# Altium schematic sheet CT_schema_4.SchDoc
size 282 x 169 mm
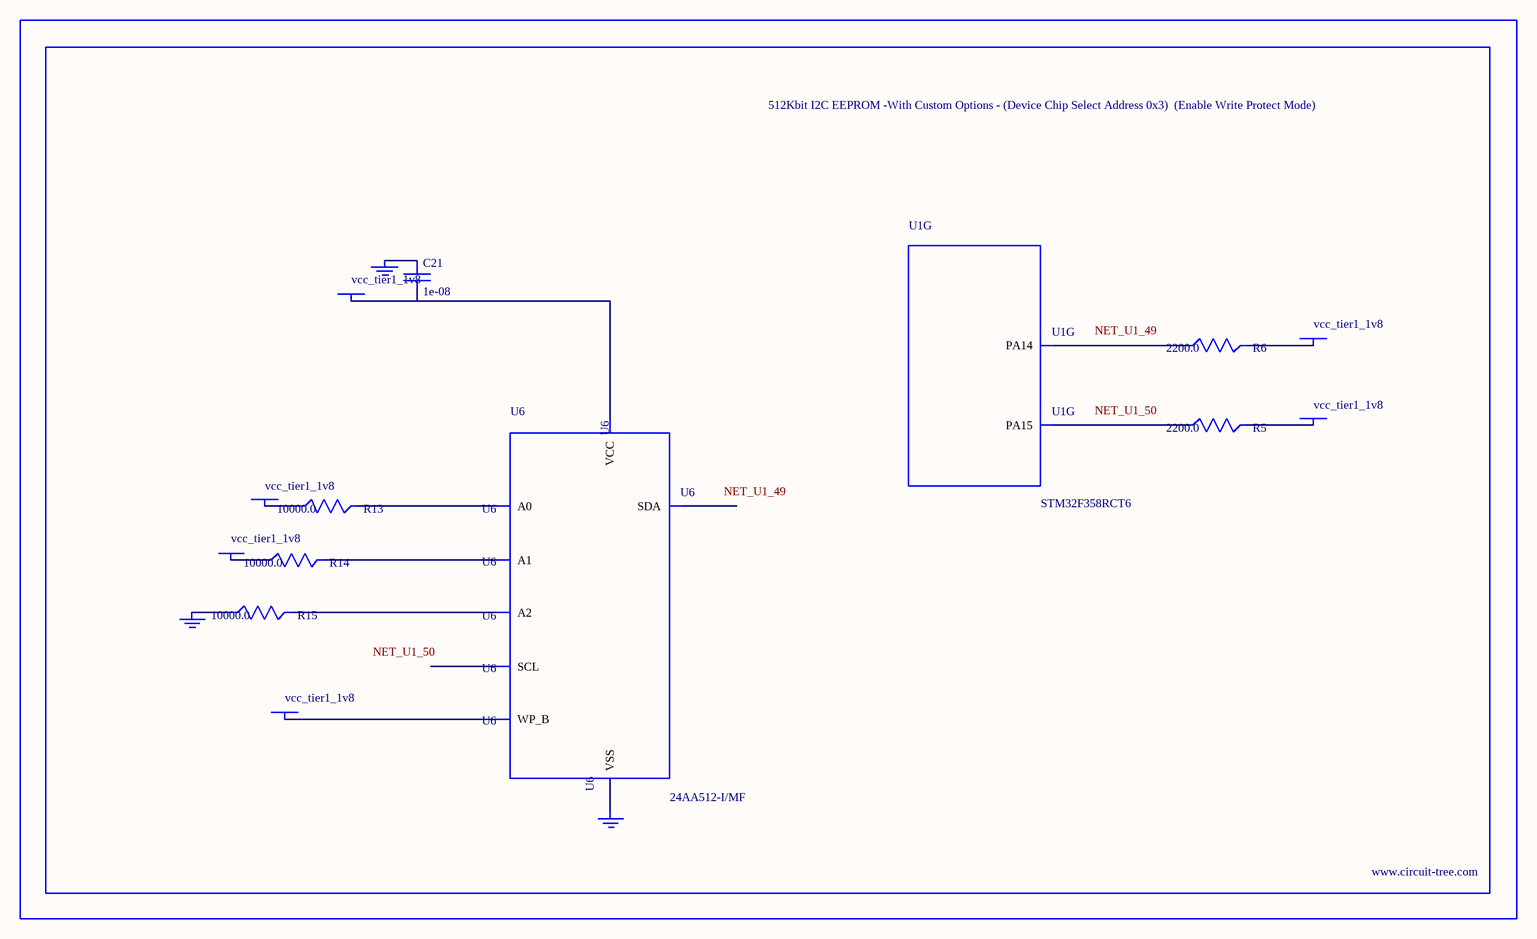
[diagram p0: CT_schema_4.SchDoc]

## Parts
BORDER3  (no value)
C21  1e-08  [C0402]
GND_INSTANCE_3_0  (no value)
GND_INSTANCE_3_1  (no value)
GND_INSTANCE_3_2  (no value)
POWER_INSTANCE_3_0  vcc_tier1_1v8
POWER_INSTANCE_3_1  vcc_tier1_1v8
POWER_INSTANCE_3_2  vcc_tier1_1v8
POWER_INSTANCE_3_3  vcc_tier1_1v8
POWER_INSTANCE_3_4  vcc_tier1_1v8
POWER_INSTANCE_3_5  vcc_tier1_1v8
R5  2200.0  [R0603]
R6  2200.0  [R0603]
R13  10000.0  [R0603]
R14  10000.0  [R0603]
R15  10000.0  [R0603]
U1  STM32F358RCT6  [LQFP64]  (part G of 7)
U6  24AA512-I/MF  [DFN8-S]

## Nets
NetC21_1: C21.1 GND_INSTANCE_3_1.0(GND)
NetC21_2: C21.2 POWER_INSTANCE_3_3.0(PWR) U6.8(VCC)
NetGND_INSTANCE_3_0_0: GND_INSTANCE_3_0.0(GND) R15.1
NetGND_INSTANCE_3_2_0: GND_INSTANCE_3_2.0(GND) U6.4(VSS)
NetPOWER_INSTANCE_3_0_0: POWER_INSTANCE_3_0.0(PWR) R13.1
NetPOWER_INSTANCE_3_1_0: POWER_INSTANCE_3_1.0(PWR) R14.1
NetPOWER_INSTANCE_3_2_0: POWER_INSTANCE_3_2.0(PWR) U6.7(WP_B)
NetPOWER_INSTANCE_3_4_0: POWER_INSTANCE_3_4.0(PWR) R6.2
NetPOWER_INSTANCE_3_5_0: POWER_INSTANCE_3_5.0(PWR) R5.2
NetR5_1: R5.1 U1.50(PA15)
NetR6_1: R6.1 U1.49(PA14)
NetR13_2: R13.2 U6.1(A0)
NetR14_2: R14.2 U6.2(A1)
NetR15_2: R15.2 U6.3(A2)

Not connected (* = marked no-connect by the designer): U6 5(SDA) 6(SCL)

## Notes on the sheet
- Labels drawn without touching a wire or pin: NET_U1_49, NET_U1_50

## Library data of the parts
BORDER3 = BORDER_PAGE3
C21 = C0402C103K3RAC
GND_INSTANCE_3_0-GND_INSTANCE_3_2 = GND
POWER_INSTANCE_3_0-POWER_INSTANCE_3_5 = PWR
R5 R6 = RC0603JR-072K2L
R13-R15 = RC0603JR-0710KL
